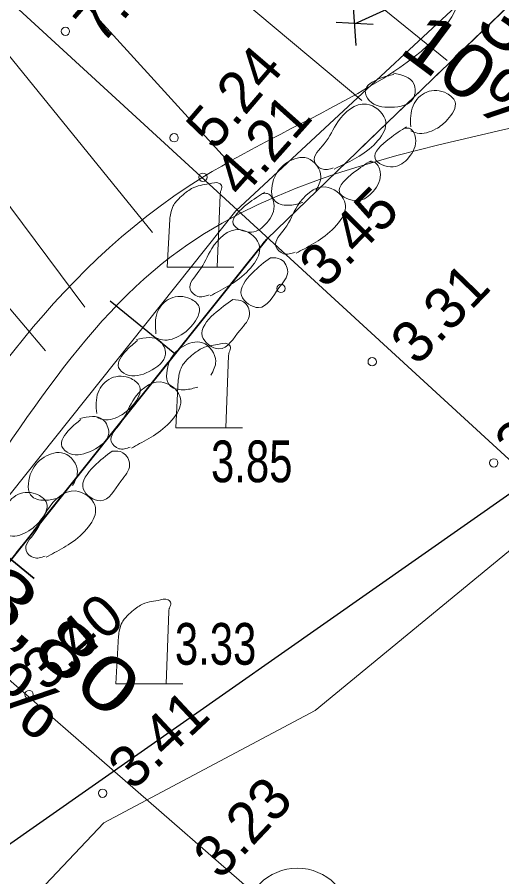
# Model space of a CAD drawing. Extents: x -1320 to -1174, y 762 to 862.
# Drawn here: x -1238.36 to -1232.55, y 811.79 to 822.09 of the extents above; entities that cross this region are included whole.
import ezdxf
from ezdxf.enums import TextEntityAlignment as Align

# ---------------------------------------------------------------- set-up
doc = ezdxf.new("R2010")
doc.units = 0
doc.header["$LTSCALE"] = 0.2
doc.linetypes.add('DOT_DASHED', pattern=[7.7, 5, -1.2, 0.3, -1.2])
for name, color, linetype, lineweight in [('1', 7, 'Continuous', 13), ('19', 7, 'Continuous', 25), ('5', 7, 'Continuous', 13), ('55', 7, 'Continuous', 13), ('6', 7, 'Continuous', 13), ('62', 7, 'Continuous', 13), ('63', 7, 'Continuous', 13)]:
    doc.layers.add(name, color=color, linetype=linetype, lineweight=lineweight)
doc.layers.add('8', color=7, linetype='Continuous')

msp = doc.modelspace()

# ---------------------------------------------------------------- linework, layer by layer
at = {"layer": '1'}
for p, q in [((-1237.718, 825.232), (-1233.202, 821.569)), ((-1241.586, 825.164), (-1230.918, 815.373)), ((-1238.484, 824.65), (-1234.223, 821.091)), ((-1238.91, 823.745), (-1235.858, 820.396)), ((-1239.583, 823.017), (-1236.735, 819.506)), ((-1240.377, 822.41), (-1237.544, 818.612)), ((-1241.164, 821.793), (-1238.014, 818.09)), ((-1247.111, 821.685), (-1235.538, 811.611))]:
    msp.add_line(p, q, dxfattribs=at)
msp.add_circle((-1234.9969, 811.255), 0.635, dxfattribs=at)
msp.add_spline([(-1235.8, 825.801), (-1237.913, 825.174), (-1239.203, 823.346), (-1241.709, 821.268), (-1246.557, 815.58), (-1256.526, 805.053), (-1260.592, 799.147), (-1261.416, 795.29), (-1262.742, 791.444), (-1262.206, 785.139)], degree=3, dxfattribs=at)
at = {"layer": '19', "lineweight": 13}
msp.add_spline([(-1253.457, 785.393), (-1253.726, 794.104), (-1251.637, 801.373), (-1250.122, 804.26), (-1247.608, 807.348), (-1239.437, 815.545), (-1236.508, 819.221), (-1228.799, 821.851), (-1223.357, 826.161), (-1220.079, 827.95)], degree=3, dxfattribs=at)
at = {"layer": '5'}
for p, q in [((-1235.958, 819.092), (-1235.924, 819.957)), ((-1235.958, 819.092), (-1236.558, 819.092)), ((-1235.958, 819.092), (-1235.758, 819.092)), ((-1235.855, 817.167), (-1235.821, 818.032)), ((-1235.855, 817.167), (-1236.455, 817.167)), ((-1235.855, 817.167), (-1235.655, 817.167)), ((-1236.571, 814.1), (-1236.537, 814.965)), ((-1236.571, 814.1), (-1237.171, 814.1)), ((-1236.571, 814.1), (-1236.371, 814.1))]:
    msp.add_line(p, q, dxfattribs=at)
for points in [[(-1236.527, 819.665), (-1236.558, 819.092), (-1236.258, 819.092), (-1235.958, 819.092)], [(-1236.424, 817.74), (-1236.455, 817.167), (-1236.155, 817.167), (-1235.855, 817.167)], [(-1237.14, 814.673), (-1237.171, 814.1), (-1236.871, 814.1), (-1236.571, 814.1)]]:
    msp.add_lwpolyline(points, dxfattribs=at)
for points in [[(-1235.924, 819.957), (-1235.92, 819.988), (-1235.917, 819.999), (-1235.902, 820.061), (-1235.932, 820.096), (-1236.054, 820.09), (-1236.158, 820.072), (-1236.264, 820.033), (-1236.329, 819.989), (-1236.404, 819.925), (-1236.484, 819.827), (-1236.515, 819.738), (-1236.527, 819.664)], [(-1235.821, 818.032), (-1235.817, 818.063), (-1235.814, 818.074), (-1235.799, 818.136), (-1235.829, 818.171), (-1235.951, 818.165), (-1236.055, 818.147), (-1236.161, 818.108), (-1236.226, 818.064), (-1236.301, 818), (-1236.381, 817.902), (-1236.412, 817.813), (-1236.424, 817.739)], [(-1236.537, 814.965), (-1236.533, 814.996), (-1236.53, 815.007), (-1236.515, 815.069), (-1236.545, 815.104), (-1236.667, 815.098), (-1236.771, 815.08), (-1236.877, 815.041), (-1236.942, 814.997), (-1237.017, 814.933), (-1237.097, 814.835), (-1237.128, 814.746), (-1237.14, 814.672)]]:
    msp.add_spline(points, degree=3, dxfattribs=at)
at = {"layer": '55'}
msp.add_lwpolyline([(-1251.178, 781.943), (-1250.876, 788.586), (-1249.424, 796.058), (-1246.365, 802.296), (-1239.008, 810.653), (-1237.317, 812.435), (-1234.783, 813.781), (-1227.269, 819.96), (-1220.231, 823.644), (-1218.172, 824.289), (-1214.858, 828.794), (-1213.694, 830.71)], dxfattribs=at)
at = {"layer": '6'}
for centre in [(-1237.777, 821.9182), (-1236.474, 820.6431), (-1236.129, 820.1692), (-1235.193, 818.8372), (-1234.1, 817.959), (-1232.6422, 816.7462), (-1238.212, 813.9701), (-1237.331, 812.7882)]:
    msp.add_circle(centre, 0.05, dxfattribs=at)
at = {"layer": '62'}
msp.add_spline([(-1254.434, 786.21), (-1255.853, 794.247), (-1253.373, 799.783), (-1252.196, 801.907), (-1252.103, 801.965), (-1250.675, 804.058), (-1247.791, 807.511), (-1245.419, 810.213), (-1244.186, 811.494), (-1242.939, 812.764), (-1240.149, 815.75), (-1236.129, 820.169), (-1233.075, 822.242), (-1235.394, 825.816)], degree=3, dxfattribs=at)
at = {"layer": '63', "lineweight": 25}
for p, q in [((-1232.6, 822.795), (-1234.316, 822.005)), ((-1234.331, 822.265), (-1234.294, 821.748)), ((-1234.533, 822.028), (-1234.09, 822.003)), ((-1236.466, 818.053), (-1237.24, 818.685))]:
    msp.add_line(p, q, dxfattribs=at)
at = {"layer": '63', "lineweight": 35}
msp.add_line((-1245.197, 821.093), (-1238.151, 815.361), dxfattribs=at)
at = {"layer": '63', "lineweight": 25}
msp.add_lwpolyline([(-1251.428, 785.238), (-1264.287, 784.95), (-1270.386, 788.761), (-1278.142, 789.522), (-1278.429, 820.376), (-1260.692, 834.371), (-1258.181, 840.695), (-1250.014, 845.483), (-1229.719, 840.992), (-1227.821, 835.408), (-1218.992, 825.806), (-1239.144, 811.691), (-1246.246, 803.626), (-1250.024, 795.415), (-1251.371, 785.665)], close=True, dxfattribs=at)
at = {"layer": '63', "linetype": 'DOT_DASHED', "lineweight": 25}
msp.add_lwpolyline([(-1254.918, 786.26), (-1254.605, 794.542), (-1253.865, 797.042), (-1252.437, 799.553), (-1250.698, 801.658), (-1245.95, 807.041), (-1239.139, 814.697), (-1235.363, 819.429), (-1232.239, 822.444), (-1231.619, 822.931), (-1231.44, 822.991), (-1229.31, 823.677), (-1223.125, 826.536)], dxfattribs=at)
at = {"layer": '63', "lineweight": 35}
msp.add_lwpolyline([(-1254.918, 786.26), (-1254.605, 794.542), (-1253.865, 797.042), (-1252.437, 799.553), (-1251.568, 800.606), (-1250.698, 801.658), (-1248.324, 804.35), (-1245.95, 807.041), (-1242.544, 810.869), (-1239.139, 814.697), (-1237.251, 817.063), (-1235.363, 819.429), (-1233.801, 820.936), (-1232.239, 822.444), (-1231.619, 822.931), (-1229.31, 823.677), (-1223.125, 826.536)], dxfattribs=at)
at = {"layer": '63'}
msp.add_lwpolyline([(-1231.863, 823.367), (-1235.734, 819.766), (-1239.521, 815.019), (-1242.918, 811.201), (-1245.916, 807.839), (-1248.699, 804.681), (-1251.078, 801.983), (-1252.85, 799.838), (-1253.787, 798.196), (-1254.328, 797.239), (-1254.328, 797.239), (-1255.102, 794.624)], dxfattribs=at)
for points in [[(-1233.847, 821.42), (-1233.601, 821.289), (-1233.607, 821.114), (-1233.871, 821.008), (-1234.135, 821.09), (-1234.183, 821.205), (-1234.011, 821.352), (-1233.839, 821.402)], [(-1233.638, 820.775), (-1233.61, 821.027), (-1233.446, 821.19), (-1233.205, 821.174), (-1233.107, 821.074), (-1233.196, 820.861), (-1233.337, 820.748), (-1233.562, 820.699), (-1233.638, 820.726)], [(-1234.566, 820.281), (-1234.705, 820.269), (-1234.792, 820.358), (-1234.676, 820.569), (-1234.511, 820.834), (-1234.17, 821.046), (-1233.945, 820.867), (-1234.225, 820.442), (-1234.452, 820.318), (-1234.554, 820.268)], [(-1233.689, 820.773), (-1233.898, 820.63), (-1234.066, 820.395), (-1233.848, 820.295), (-1233.664, 820.404), (-1233.58, 820.639), (-1233.655, 820.756), (-1233.714, 820.756)], [(-1234.774, 820.01), (-1234.716, 820.176), (-1234.876, 820.397), (-1235.114, 820.35), (-1235.281, 820.143), (-1235.26, 819.878), (-1235.082, 819.835), (-1234.931, 819.866)], [(-1234.113, 820.368), (-1234.322, 820.225), (-1234.49, 819.99), (-1234.272, 819.89), (-1234.088, 819.999), (-1234.004, 820.234), (-1234.079, 820.351), (-1234.138, 820.351)], [(-1235.025, 819.271), (-1235.163, 819.253), (-1235.254, 819.338), (-1235.148, 819.554), (-1234.995, 819.826), (-1234.663, 820.053), (-1234.431, 819.884), (-1234.691, 819.447), (-1234.913, 819.313), (-1235.012, 819.258)], [(-1235.388, 819.991), (-1235.597, 819.848), (-1235.765, 819.613), (-1235.547, 819.513), (-1235.363, 819.622), (-1235.279, 819.857), (-1235.354, 819.974), (-1235.413, 819.974)], [(-1236.053, 818.76), (-1236.191, 818.742), (-1236.282, 818.827), (-1236.176, 819.043), (-1236.023, 819.315), (-1235.691, 819.542), (-1235.459, 819.373), (-1235.719, 818.936), (-1235.941, 818.802), (-1236.04, 818.747)], [(-1235.32, 819.205), (-1235.54, 819.02), (-1235.667, 818.751), (-1235.461, 818.608), (-1235.217, 818.844), (-1235.112, 819.038), (-1235.193, 819.185), (-1235.32, 819.205)], [(-1236.692, 818.294), (-1236.676, 818.547), (-1236.519, 818.717), (-1236.278, 818.712), (-1236.175, 818.616), (-1236.255, 818.399), (-1236.39, 818.28), (-1236.613, 818.221), (-1236.69, 818.245)], [(-1235.77, 818.703), (-1235.998, 818.528), (-1236.137, 818.265), (-1235.937, 818.113), (-1235.683, 818.338), (-1235.569, 818.527), (-1235.644, 818.678), (-1235.77, 818.703)], [(-1236.926, 818.226), (-1236.648, 818.211), (-1236.578, 818.05), (-1236.773, 817.842), (-1237.047, 817.806), (-1237.139, 817.89), (-1237.045, 818.095), (-1236.911, 818.213)], [(-1236.033, 817.799), (-1235.975, 817.965), (-1236.135, 818.186), (-1236.373, 818.139), (-1236.54, 817.932), (-1236.519, 817.667), (-1236.341, 817.624), (-1236.19, 817.655)], [(-1237.402, 817.338), (-1237.386, 817.591), (-1237.229, 817.761), (-1236.988, 817.756), (-1236.885, 817.66), (-1236.965, 817.443), (-1237.1, 817.324), (-1237.323, 817.265), (-1237.4, 817.289)], [(-1236.999, 816.935), (-1237.137, 816.917), (-1237.228, 817.002), (-1237.122, 817.218), (-1236.969, 817.49), (-1236.637, 817.717), (-1236.405, 817.548), (-1236.665, 817.111), (-1236.887, 816.977), (-1236.986, 816.922)], [(-1237.606, 817.28), (-1237.328, 817.265), (-1237.258, 817.104), (-1237.453, 816.896), (-1237.727, 816.86), (-1237.819, 816.944), (-1237.725, 817.149), (-1237.591, 817.267)], [(-1237.691, 816.474), (-1237.633, 816.64), (-1237.793, 816.861), (-1238.031, 816.814), (-1238.198, 816.607), (-1238.177, 816.342), (-1237.999, 816.299), (-1237.848, 816.33)], [(-1237.216, 816.889), (-1237.436, 816.704), (-1237.563, 816.435), (-1237.357, 816.292), (-1237.113, 816.528), (-1237.008, 816.722), (-1237.089, 816.869), (-1237.216, 816.889)], [(-1238.519, 815.945), (-1238.503, 816.198), (-1238.346, 816.368), (-1238.105, 816.363), (-1238.002, 816.267), (-1238.082, 816.05), (-1238.217, 815.931), (-1238.44, 815.872), (-1238.517, 815.896)], [(-1238.02, 815.629), (-1238.158, 815.611), (-1238.249, 815.696), (-1238.143, 815.912), (-1237.99, 816.184), (-1237.658, 816.411), (-1237.426, 816.242), (-1237.686, 815.805), (-1237.908, 815.671), (-1238.007, 815.616)]]:
    msp.add_spline(points, degree=3, dxfattribs=at)

# ---------------------------------------------------------------- texts
for s, rotation, width, p in [('3,90', 326.87, 1.25, (-1232.0249, 821.3525)), ('10%', 323.374, 1.15, (-1233.0069, 821.0907)), ('3,80', 319.946, 1.35, (-1238.0789, 814.3724)), ('10%', 323.374, 1.15, (-1238.8684, 813.9721))]:
    msp.add_text(s, height=0.64, rotation=rotation, dxfattribs=dict(at, width=width)).set_placement(p, align=Align.CENTER)
at = {"layer": '8'}
for s, rotation, p in [(' 7.07', 49.117, (-1237.461, 821.606)), (' 5.24', 49.445, (-1236.11, 820.334)), (' 4.21', 48.26, (-1235.787, 819.765)), (' 3.45', 45.114, (-1234.795, 818.69)), (' 3.31', 46.023, (-1233.69, 817.764)), (' 3.42', 41.398, (-1232.484, 816.565)), (' 3.40', 40.947, (-1238.161, 813.869)), (' 3.41', 43.053, (-1237.106, 812.681)), (' 3.23', 46.533, (-1236.049, 811.604))]:
    msp.add_text(s, height=0.5, rotation=rotation, dxfattribs=at).set_placement(p)
at = {"layer": '8', "width": 0.75}
for s, p in [(' 3.85', (-1236.171, 816.515)), (' 3.33', (-1236.604, 814.328))]:
    msp.add_text(s, height=0.5, dxfattribs=at).set_placement(p)

doc.saveas('drawing.dxf')
